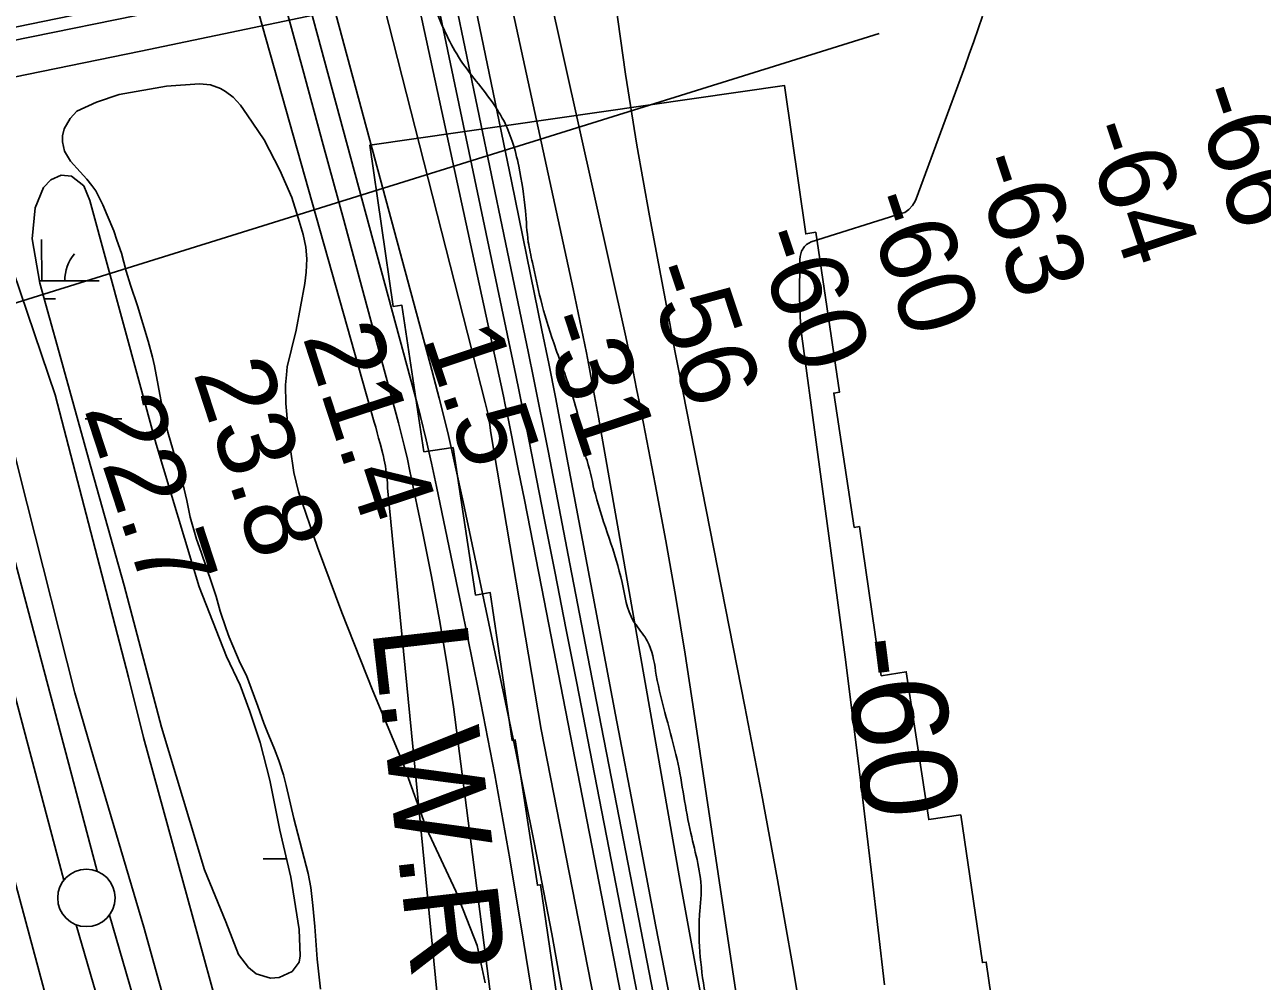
# Model space of a CAD drawing. Extents: x 3405885 to 3443815, y 558517 to 583997.
# Drawn here: x 3412665 to 3413741, y 580269 to 581101 of the extents above; entities that cross this region are included whole.
import ezdxf

# ---------------------------------------------------------------- set-up
doc = ezdxf.new("R2010")
doc.units = 0
for name, color, linetype in [('V-BRDG-OTLN', 7, 'Continuous'), ('V-FLOD-BASE', 7, 'Continuous'), ('V-LEVE-TOET', 7, 'Continuous'), ('V-RIVR-EDGE', 7, 'Continuous'), ('V-RIVR-RANG', 7, 'Continuous'), ('V-ROAD-CNTR', 7, 'Continuous'), ('V-RRAP-RVMT', 7, 'Continuous'), ('V-SITE-VEGE', 7, 'Continuous'), ('V-SURV-LINE', 7, 'Continuous'), ('V-TOPO-DPTH', 7, 'Continuous'), ('V-TOPO-MAJR', 7, 'Continuous'), ('V-TOPO-MINR', 7, 'Continuous'), ('V-TOPO-MINR-IDEN', 7, 'Continuous'), ('V-TOPO-WATR', 7, 'Continuous'), ('V-TOPO-WATR-IDEN', 7, 'Continuous'), ('V-WETL-SWMP', 7, 'Continuous')]:
    doc.layers.add(name, color=color, linetype=linetype)

msp = doc.modelspace()

# ---------------------------------------------------------------- linework, layer by layer
at = {"layer": 'V-BRDG-OTLN'}
for points in [[(3417680.4, 582119.8), (3417601.8, 582104.6), (3417266, 582031.9), (3417072.3, 581991.6), (3416368.4, 581849.5), (3415729.2, 581717.9), (3415183.5, 581606.5), (3414289.2, 581422.5), (3413599.8, 581283.7), (3412908.9, 581139.2), (3412266.4, 581008.4), (3412181.4, 580990.5), (3412075.2, 580969.3), (3411951.8, 580944.2), (3411795.1, 580912.3), (3411642, 580880.6), (3411498.5, 580851.2), (3411034.3, 580756.7), (3410912.4, 580731.2)], [(3411677.7, 580918.3), (3412408.2, 581067.1), (3413000.1, 581190.8), (3413110.1, 581213.7), (3413121.5, 581152.9), (3412941.9, 581114.8), (3412765.6, 581078.1), (3412568.7, 581037.8), (3412280.7, 580978.9), (3411914.4, 580903.8)]]:
    msp.add_lwpolyline(points, dxfattribs=at)
at = {"layer": 'V-FLOD-BASE'}
for points in [[(3412708.3, 580519.9), (3412667, 580684), (3412637.7, 580799.6), (3412608.4, 580882.1), (3412552.9, 581031.3), (3412536.3, 581093.7), (3412510.6, 581183), (3412508.1, 581194.1)], [(3412809.2, 580169), (3412768.3, 580316.1), (3412724.5, 580463.8), (3412708.3, 580519.9)]]:
    msp.add_lwpolyline(points, dxfattribs=at)
at = {"layer": 'V-LEVE-TOET'}
for points in [[(3412547.5, 581149.2), (3412570.5, 581062.7), (3412585.1, 581037.6), (3412612.5, 580998.5), (3412621, 580972.1), (3412655, 580886), (3412691.3, 580779.2), (3412755.1, 580533.4), (3412767.9, 580481)], [(3412611.9, 580517.9), (3412657.3, 580352), (3412706.8, 580167.1), (3412733.3, 580061.4), (3412768.8, 579901.4), (3412809.4, 579723.1), (3412854.8, 579541.2), (3412909.9, 579317.4), (3412945.5, 579162.7), (3412960.5, 579105.7)], [(3412767.9, 580481), (3412806.4, 580341.6), (3412860.6, 580143.7), (3412871.5, 580101.8), (3412901.2, 579957.1), (3412913, 579869.8), (3412926, 579791.3), (3412952.9, 579666.1), (3412992.6, 579509), (3413041.3, 579299.4), (3413080.9, 579138.2), (3413128.6, 578952.8), (3413181, 578759.6), (3413225.8, 578579.5), (3413232.6, 578542.3)]]:
    msp.add_lwpolyline(points, dxfattribs=at)
at = {"layer": 'V-RIVR-EDGE'}
msp.add_spline([(3412820.9, 582098.3), (3412817.8, 582058), (3412815.6, 582029.5), (3412817.7, 582007.9), (3412825.7, 581980.1), (3412850.3, 581879.9), (3412863.7, 581832.7), (3412872, 581799.1), (3412892.3, 581722.3), (3412903.2, 581678.4), (3412909.6, 581634.8), (3412920.5, 581599), (3412934, 581569.3), (3412943.4, 581548.5), (3412954.7, 581511.2), (3412955.3, 581484.9), (3412959.7, 581464), (3412965.1, 581459.6), (3412977.9, 581445), (3412992.4, 581409.1), (3413006.5, 581353.1), (3413015.2, 581302.3), (3413018.7, 581260.3), (3413013.9, 581236.1), (3413008.8, 581220.1), (3413005.1, 581206.5), (3413003.6, 581194.5), (3413004.7, 581180.2), (3413009.3, 581149.1), (3413020.6, 581117.3), (3413042, 581073), (3413073, 581031.3), (3413081, 581018.1), (3413088.7, 580999.8), (3413094.4, 580977.9), (3413100.2, 580939.1), (3413102.7, 580912), (3413106.3, 580894.1), (3413113.5, 580861.9), (3413124.8, 580824.3), (3413140, 580781.4), (3413146.5, 580756.9), (3413148.7, 580740.1), (3413153.8, 580721.8), (3413161, 580692.6), (3413184.2, 580615.7), (3413194, 580582.5), (3413204.2, 580568.2), (3413207.8, 580561.6), (3413214, 580535.3), (3413232.1, 580461.7), (3413244, 580397.7), (3413253, 580345.1), (3413251.9, 580330.8), (3413256.4, 580258.4), (3413262.5, 580217.5), (3413264.6, 580175.4), (3413271.5, 580146.5), (3413278.7, 580117.3), (3413280.2, 580104.8), (3413276.4, 580060.6), (3413276.3, 580025.9), (3413275.6, 580012.4), (3413275.5, 580006.1), (3413277.7, 580003.2), (3413288, 580000.6), (3413298.6, 579998.4), (3413303.7, 579992.2), (3413305.5, 579985.2), (3413310.1, 579953.8), (3413314.5, 579931.1), (3413321, 579914.6), (3413327.2, 579894.5), (3413327.1, 579868.9), (3413323.4, 579842.6), (3413317.9, 579835.3), (3413316, 579824.7), (3413315.6, 579806.5), (3413320, 579780.1), (3413328, 579765.1), (3413335.6, 579758.2), (3413338.2, 579753.4), (3413338.9, 579747.5), (3413338.9, 579742.8), (3413335.5, 579730.7), (3413330.8, 579723.1), (3413327.8, 579714.3), (3413325.2, 579701.2), (3413326.7, 579689.5), (3413332.1, 579675.9), (3413338.3, 579668.2), (3413342.7, 579666.4), (3413352.6, 579666.7), (3413357.3, 579663.4), (3413365.3, 579652.4), (3413371.9, 579635.2), (3413374.8, 579618.4), (3413377.6, 579592.5), (3413379.4, 579557.4), (3413373.8, 579521.6), (3413375.2, 579501.1), (3413382.1, 579476.9), (3413395.1, 579440), (3413408.6, 579400.8), (3413417.6, 579358.8), (3413445.2, 579297.7), (3413449.9, 579271.7), (3413449.8, 579233.3), (3413439.5, 579191.3), (3413438.7, 579182.2), (3413439.8, 579172.7), (3413446, 579161.7), (3413464.9, 579134.6), (3413487.5, 579101.6), (3413497, 579074.9), (3413502.7, 579046.4), (3413506.7, 579018.2), (3413510.6, 578990.8), (3413518.6, 578952.4), (3413529.8, 578903.8), (3413538.1, 578871.6), (3413547.9, 578834.6), (3413558.4, 578787.4), (3413566.7, 578743.2), (3413574.6, 578699.3), (3413585.1, 578637.1), (3413595.2, 578577.2), (3413599.5, 578547.5), (3413610.7, 578516.1), (3413620.2, 578504), (3413626, 578499.2), (3413635.5, 578497), (3413635.9, 578494.4), (3413634.1, 578490.1), (3413632.2, 578487.1), (3413632.2, 578479.5), (3413633.2, 578455), (3413642.2, 578391), (3413644.3, 578359.2), (3413649, 578338.7), (3413656.3, 578322.2), (3413667.6, 578313.8), (3413676, 578309), (3413684.4, 578305.3), (3413688.8, 578300.2), (3413697.9, 578288.5), (3413702.2, 578272.4), (3413709.1, 578250.8), (3413714.9, 578233.2), (3413728.7, 578187.2), (3413734.8, 578151.3), (3413738.8, 578114.4), (3413740.5, 578084), (3413746.7, 578059.2), (3413750.7, 578043.4), (3413751.3, 578020), (3413747.6, 577990.8), (3413742, 577955), (3413736.9, 577934.5), (3413735.4, 577919.6), (3413733.5, 577904.2), (3413737.1, 577880.1), (3413741.4, 577864.7), (3413741.4, 577863.2), (3413750.2, 577865.8), (3413755, 577862.8), (3413760, 577845.7), (3413773.8, 577798.1), (3413781.8, 577765.2), (3413793, 577724.9), (3413797, 577700.4), (3413803.4, 577637.2), (3413804.4, 577613.8), (3413807.7, 577591.8), (3413815.3, 577561.1), (3413829.4, 577524.9), (3413841.8, 577493.8), (3413853.8, 577466), (3413863.2, 577445.5), (3413869.8, 577431.2), (3413869.8, 577426.1), (3413869.7, 577412.9), (3413868.9, 577389.5), (3413869.2, 577353), (3413871, 577339.8), (3413873.9, 577328.5), (3413883, 577306.5), (3413889.5, 577287.9), (3413905.1, 577244.3), (3413913.5, 577211), (3413925.4, 577161.3), (3413947.6, 577101.7), (3413958.8, 577073.5), (3413969, 577057.4), (3413973, 577043.8), (3413979.9, 577014.6), (3414002, 576930.8), (3414004.5, 576907.4), (3414006.3, 576897.2), (3414015, 576880.3), (3414024.5, 576858.8), (3414031.3, 576835.7), (3414040.8, 576799.5), (3414054.2, 576750.1), (3414062.5, 576713.9), (3414069.3, 576679.9), (3414074.4, 576668.5), (3414075.1, 576663.4), (3414103.1, 576586.2), (3414107.4, 576564.6), (3414115.4, 576529.2), (3414119, 576508), (3414142.2, 576433.7), (3414153.5, 576399.3), (3414159.6, 576378.5), (3414164.7, 576348.8), (3414174.1, 576303.8), (3414178, 576275), (3414184.1, 576248.3), (3414191.1, 576234), (3414204.1, 576202.1), (3414212.1, 576179.5), (3414243, 576089.5), (3414264.8, 576025.4), (3414269.5, 576005.7), (3414269.4, 575994.4), (3414267.6, 575989.1)], degree=3, dxfattribs=at)
at = {"layer": 'V-RIVR-RANG'}
msp.add_line((3412586.8, 580837.2), (3413407.7, 581093.5), dxfattribs=at)
at = {"layer": 'V-ROAD-CNTR'}
msp.add_lwpolyline([(3409957, 580546.7), (3410940.8, 580747.1), (3417648.2, 582122.8)], dxfattribs=at)
at = {"layer": 'V-RRAP-RVMT'}
msp.add_lwpolyline([(3413519.8, 580156.2), (3413500.9, 580285.6), (3413497.6, 580285.1), (3413478.8, 580413.6), (3413451, 580409.5), (3413431.3, 580538.2), (3413409.6, 580534.7), (3413390.6, 580664.4), (3413386.1, 580663.7), (3413368.3, 580780.6), (3413373.3, 580781.3), (3413352.6, 580920.5), (3413344, 580919.1), (3413325.4, 581048.3), (3412964.9, 580996.3), (3412985.2, 580855.9), (3412992.8, 580857), (3413011.9, 580729.6), (3413037.2, 580733.2), (3413056.8, 580604.9), (3413069.6, 580607), (3413088.6, 580478.4), (3413091.3, 580478.9), (3413110.6, 580352.4), (3413113.3, 580352.9), (3413130.9, 580232.1)], dxfattribs=at)
at = {"layer": 'V-SITE-VEGE'}
for points in [[(3412727.3, 581033.8), (3412746.9, 581040.3), (3412788, 581047.5), (3412816.7, 581049.6), (3412826.2, 581048.8), (3412835, 581045.5), (3412839.4, 581043), (3412846.1, 581038), (3412852.3, 581031.1), (3412858.3, 581022.6), (3412873.1, 581001), (3412886.7, 580974.4), (3412896.9, 580950.8), (3412902.5, 580933), (3412907, 580918.4), (3412909.1, 580907.5), (3412910.2, 580897.4), (3412909.6, 580885.8), (3412908.3, 580875.8), (3412900.7, 580835.4), (3412896.7, 580818.9), (3412893.1, 580803.4), (3412892.5, 580796.5), (3412891.6, 580787.9), (3412891.9, 580771.6), (3412893.6, 580752.2), (3412895.6, 580733.4), (3412898.8, 580711.4), (3412902.8, 580694.7), (3412919.3, 580646.6), (3412940.6, 580589.6), (3412967.5, 580521.5), (3412993.2, 580459.7), (3413014.1, 580401.8)], [(3412921.9, 580262.1), (3412919.2, 580288), (3412917, 580316.4), (3412915.3, 580334.7), (3412913.7, 580350.6), (3412911.3, 580362.6), (3412898.9, 580410.5), (3412892.2, 580439.2), (3412889.7, 580448.6), (3412885.6, 580460.9), (3412882, 580470.8), (3412875.5, 580486.2), (3412872.6, 580493.3), (3412867.4, 580508.2), (3412861.7, 580523.9), (3412857.6, 580534.8), (3412852.2, 580545.7), (3412842.5, 580568.1), (3412839.8, 580575.6), (3412834.6, 580591), (3412831.1, 580603.6), (3412827.5, 580615), (3412818.1, 580642.1), (3412814, 580653.5), (3412808.5, 580672.5), (3412805.7, 580687), (3412802.2, 580701.8), (3412797.8, 580715), (3412793.8, 580730.5), (3412789.2, 580746.6), (3412784.1, 580770.1), (3412777.7, 580804.3), (3412775.8, 580811.9), (3412772, 580825.8), (3412762.7, 580856.5), (3412756.7, 580874.5), (3412753, 580886.6), (3412748.9, 580902.2), (3412744.7, 580913.6), (3412742.1, 580921.7), (3412736.5, 580935.4), (3412732.8, 580944.3), (3412726.5, 580956.4), (3412723.1, 580961.3), (3412718.7, 580966.8), (3412712.9, 580973), (3412704.6, 580982.4), (3412699.4, 580991.1), (3412697.7, 580999.2), (3412697.6, 581004.4), (3412699.1, 581010.4), (3412704.3, 581019.5), (3412710, 581025.7), (3412727.3, 581033.8)], [(3413014.1, 580401.8), (3413039.7, 580347.4), (3413058.3, 580300.1), (3413065.2, 580267.6)]]:
    msp.add_lwpolyline(points, dxfattribs=at)
at = {"layer": 'V-SURV-LINE'}
for points in [[(3412345.3, 581807.9), (3412727.8, 580364.6)], [(3412698.8, 580356.9), (3412316.3, 581800.2)], [(3412738.4, 580326.4), (3412853.9, 579928.2)], [(3412825.1, 579919.9), (3412709.6, 580318)]]:
    msp.add_lwpolyline(points, dxfattribs=at)
msp.add_circle((3412718.4, 580341.4), 25, dxfattribs=at)
at = {"layer": 'V-TOPO-DPTH'}
for points in [[(3412664.9, 582099.7), (3412797.7, 581548.5), (3412800.3, 581537.6), (3412803.1, 581526.7), (3412805.9, 581515.8), (3412808.7, 581505), (3412840.5, 581386.1), (3412859.4, 581315.8), (3412878.2, 581245.6), (3412897.1, 581175.3), (3412916, 581105.1), (3413003.6, 580780.3), (3413008.8, 580760.2), (3413013.8, 580740), (3413018.5, 580719.7), (3413022.9, 580699.3), (3413044.7, 580594.5), (3413059.4, 580521.5), (3413073.5, 580448.5), (3413086.5, 580375.3), (3413098.9, 580302), (3413146, 580011.8)], [(3412709.1, 582099.9), (3412741.1, 581971.9), (3412821.3, 581676.2), (3412865.2, 581528.8), (3412947.1, 581235.7), (3413065.1, 580772.3), (3413068.5, 580759.5), (3413070.2, 580745.9), (3413113.8, 580487.8), (3413186.9, 580114.7)], [(3413186.9, 580114.7), (3413113.8, 580487.8), (3413070.2, 580745.9), (3413068.5, 580759.5), (3413065.1, 580772.3), (3412947.1, 581235.7), (3412865.2, 581528.8), (3412821.3, 581676.2), (3412741.1, 581971.9), (3412709.1, 582099.9)], [(3413254.4, 580247.2), (3413244.5, 580301.5), (3413234.8, 580355.8), (3413163.6, 580759.6), (3413161.1, 580773.6), (3413158.5, 580787.6), (3413155.9, 580801.6), (3413153.2, 580815.6), (3413150.4, 580829.5), (3413147.6, 580843.5), (3413144.7, 580857.4), (3413141.7, 580871.3), (3413003.1, 581509.2), (3412995.7, 581543.2), (3412988.2, 581577.3), (3412980.7, 581611.3), (3412973.1, 581645.3), (3412871.6, 582100.6)], [(3413254.4, 580247.2), (3413244.5, 580301.5), (3413234.8, 580355.8), (3413163.6, 580759.6), (3413161.1, 580773.6), (3413158.5, 580787.6), (3413155.9, 580801.6), (3413153.2, 580815.6), (3413150.4, 580829.5), (3413147.6, 580843.5), (3413144.7, 580857.4), (3413141.7, 580871.3), (3413003.1, 581509.2), (3412995.7, 581543.2), (3412988.2, 581577.3), (3412980.7, 581611.3), (3412973.1, 581645.3), (3412871.6, 582100.6)], [(3413025.1, 581558.9), (3413187.4, 580829.4), (3413190.6, 580814.4), (3413193.8, 580799.3), (3413196.9, 580784.2), (3413199.9, 580769.1), (3413213, 580701.2), (3413222.2, 580652), (3413231, 580602.8), (3413239.1, 580553.5), (3413246.7, 580504), (3413278.8, 580288.6), (3413283.7, 580255.8)], [(3413025.1, 581558.9), (3413187.4, 580829.4), (3413190.6, 580814.4), (3413193.8, 580799.3), (3413196.9, 580784.2), (3413199.9, 580769.1), (3413213, 580701.2), (3413222.2, 580652), (3413231, 580602.8), (3413239.1, 580553.5), (3413246.7, 580504), (3413278.8, 580288.6), (3413283.7, 580255.8)], [(3412963.3, 581408.5), (3413091.7, 580796.3), (3413094.7, 580781.9), (3413097.6, 580767.5), (3413100.5, 580753.2), (3413103.4, 580738.8), (3413116.6, 580671.8), (3413126, 580624), (3413135.4, 580576.1), (3413144.8, 580528.2), (3413154.1, 580480.3), (3413239, 580043.8)], [(3413239, 580043.8), (3413154.1, 580480.3), (3413144.8, 580528.2), (3413135.4, 580576.1), (3413126, 580624), (3413116.6, 580671.8), (3413103.4, 580738.8), (3413100.5, 580753.2), (3413097.6, 580767.5), (3413094.7, 580781.9), (3413091.7, 580796.3), (3412963.3, 581408.5)], [(3413231.5, 580224.5), (3413213.7, 580316.6), (3413196.1, 580408.6), (3413178.5, 580500.7), (3413161.1, 580592.8), (3413137.4, 580718.5), (3413131.9, 580747.7), (3413126.2, 580777), (3413120.4, 580806.2), (3413114.5, 580835.4), (3413088.1, 580965), (3413068.7, 581058.9), (3413049.1, 581152.8)], [(3413049.1, 581152.8), (3413068.7, 581058.9), (3413088.1, 580965), (3413114.5, 580835.4), (3413120.4, 580806.2), (3413126.2, 580777), (3413131.9, 580747.7), (3413137.4, 580718.5), (3413161.1, 580592.8), (3413178.5, 580500.7), (3413196.1, 580408.6), (3413213.7, 580316.6), (3413231.5, 580224.5)]]:
    msp.add_lwpolyline(points, dxfattribs=at)
at = {"layer": 'V-TOPO-MAJR'}
msp.add_lwpolyline([(3413345.6, 580206.1), (3413332.7, 580281.7), (3413319.4, 580357.2), (3413305.4, 580432.5), (3413291, 580507.8), (3413237.1, 580782.2), (3413234.2, 580796.9), (3413231.3, 580811.6), (3413228.5, 580826.3), (3413225.7, 580841.1), (3413208, 580934.7), (3413197.1, 580996.3), (3413187.1, 581058.1), (3413178.6, 581120.1)], dxfattribs=at)
at = {"layer": 'V-TOPO-MINR'}
for points in [[(3412664.9, 582099.7), (3412797.7, 581548.5), (3412800.3, 581537.6), (3412803.1, 581526.7), (3412805.9, 581515.8), (3412808.7, 581505), (3412840.5, 581386.1), (3412859.4, 581315.8), (3412878.2, 581245.6), (3412897.1, 581175.3), (3412916, 581105.1), (3413003.6, 580780.3), (3413008.8, 580760.2), (3413013.8, 580740), (3413018.5, 580719.7), (3413022.9, 580699.3), (3413044.7, 580594.5), (3413059.4, 580521.5), (3413073.5, 580448.5), (3413086.5, 580375.3), (3413098.9, 580302), (3413146, 580011.8)], [(3412687.5, 582099.8), (3412743.8, 581861), (3412756.7, 581806.1), (3412769.7, 581751.2), (3412782.7, 581696.4), (3412795.7, 581641.5), (3412821, 581534.7), (3412821.4, 581533.3), (3412822.5, 581528.9), (3412826.8, 581512.5), (3412829.4, 581502.8), (3412832, 581493.1), (3412834.6, 581483.5), (3412837.2, 581473.8), (3413017.4, 580806), (3413025.2, 580776.1), (3413032.6, 580746.2), (3413039.5, 580716.1), (3413046.1, 580686), (3413091.7, 580468.9), (3413107.8, 580389.6), (3413123.1, 580310.3), (3413137.4, 580230.7)], [(3412871.6, 582100.6), (3412973.1, 581645.3), (3412980.7, 581611.3), (3412988.2, 581577.3), (3412995.7, 581543.2), (3413003.1, 581509.2), (3413141.7, 580871.3), (3413144.7, 580857.4), (3413147.6, 580843.5), (3413150.4, 580829.5), (3413153.2, 580815.6), (3413155.9, 580801.6), (3413158.5, 580787.6), (3413161.1, 580773.6), (3413163.6, 580759.6), (3413234.8, 580355.8), (3413244.5, 580301.5), (3413254.4, 580247.2)], [(3413283.7, 580255.8), (3413278.8, 580288.6), (3413246.7, 580504), (3413239.1, 580553.5), (3413231, 580602.8), (3413222.2, 580652), (3413213, 580701.2), (3413199.9, 580769.1), (3413196.9, 580784.2), (3413193.8, 580799.3), (3413190.6, 580814.4), (3413187.4, 580829.4), (3413025.1, 581558.9)], [(3412774.5, 581443.9), (3412968.7, 580755.4), (3412970, 580750.8), (3412971.3, 580746.1), (3412972.5, 580741.5), (3412973.8, 580736.8), (3412975.9, 580729), (3412976.3, 580727.5), (3412976.4, 580726.8), (3412977.4, 580722.2), (3412977.9, 580719.6), (3412978.4, 580716.9), (3412978.8, 580714.2), (3412979.4, 580709.4), (3412979.8, 580705.7), (3412980.1, 580701.9), (3412980.3, 580698.2), (3413049.8, 579987.7)], [(3412963.3, 581408.5), (3413091.7, 580796.3), (3413094.7, 580781.9), (3413097.6, 580767.5), (3413100.5, 580753.2), (3413103.4, 580738.8), (3413116.6, 580671.8), (3413126, 580624), (3413135.4, 580576.1), (3413144.8, 580528.2), (3413154.1, 580480.3), (3413239, 580043.8)], [(3413027.9, 581176.9), (3413102.8, 580815.4), (3413107.2, 580793.8), (3413111.6, 580772.2), (3413115.9, 580750.5), (3413120.1, 580728.9), (3413138.8, 580631.9), (3413152.4, 580561.7), (3413166, 580491.5), (3413179.6, 580421.4), (3413193.2, 580351.2), (3413245.4, 580081.8)], [(3413049.1, 581152.8), (3413068.7, 581058.9), (3413088.1, 580965), (3413114.5, 580835.4), (3413120.4, 580806.2), (3413126.2, 580777), (3413131.9, 580747.7), (3413137.4, 580718.5), (3413161.1, 580592.8), (3413178.5, 580500.7), (3413196.1, 580408.6), (3413213.7, 580316.6), (3413231.5, 580224.5)], [(3412888.5, 581127.8), (3412906.5, 581062.2), (3412924.4, 580996.6), (3412942.2, 580930.9), (3412960, 580865.2), (3412989.7, 580754.7), (3412992.4, 580744.2), (3412995, 580733.7), (3412997.5, 580723.2), (3412999.7, 580712.7), (3413011, 580658.7), (3413018.4, 580621), (3413025.4, 580583.3), (3413031.7, 580545.5), (3413037.5, 580507.5), (3413104.9, 579984.7)], [(3413006.3, 581123.6), (3413081, 580777.9), (3413082.6, 580770.5), (3413084.2, 580763.1), (3413085.7, 580755.7), (3413087.2, 580748.2), (3413094.3, 580712.8), (3413099.3, 580687.6), (3413104.3, 580662.4), (3413109.2, 580637.2), (3413114.2, 580612.1), (3413208, 580129.1)], [(3413497.8, 581108.6), (3413494, 581097.5), (3413490.1, 581086.4), (3413486.2, 581075.3), (3413482.2, 581064.3), (3413440, 580949.7), (3413439.1, 580947.6), (3413436.8, 580943.7), (3413433.7, 580940.3), (3413430, 580937.8), (3413427.9, 580937), (3413348.8, 580912.2), (3413344.6, 580909.9), (3413342.9, 580908.2), (3413340.4, 580904), (3413339.2, 580899.3), (3413338.9, 580896.9), (3413338.6, 580864.1), (3413338.7, 580855.5), (3413339, 580847), (3413339.7, 580838.5), (3413340.7, 580830), (3413365.6, 580645.8), (3413378.1, 580550.9), (3413390.1, 580455.9), (3413401.5, 580360.9), (3413412.4, 580265.8)]]:
    msp.add_lwpolyline(points, dxfattribs=at)
at = {"layer": 'V-TOPO-WATR'}
msp.add_lwpolyline([(3413186.9, 580114.7), (3413113.8, 580487.8), (3413070.2, 580745.9), (3413068.5, 580759.5), (3413065.1, 580772.3), (3412947.1, 581235.7), (3412865.2, 581528.8), (3412821.3, 581676.2), (3412741.1, 581971.9), (3412709.1, 582099.9)], dxfattribs=at)
at = {"layer": 'V-WETL-SWMP'}
for p, q in [((3412679.5, 580878.1), (3412679.4, 580914.1)), ((3412677.6, 580878.1), (3412729.5, 580878.3)), ((3412681.7, 580862.7), (3412691.6, 580862.7)), ((3412717.2, 580758.2), (3412749.2, 580758.3)), ((3412872, 580375.4), (3412892.4, 580375.4))]:
    msp.add_line(p, q, dxfattribs=at)
msp.add_lwpolyline([(3412839.5, 580320.7), (3412821.1, 580365.8), (3412783.7, 580490), (3412751.1, 580613.3), (3412720.3, 580723.6), (3412694.6, 580815.8), (3412678, 580876.1), (3412671.2, 580914.8), (3412673.8, 580941.7), (3412681.1, 580959.4), (3412687.4, 580966.2), (3412696.4, 580970.1), (3412705.4, 580969.3), (3412716.2, 580960.8), (3412721.5, 580948.2), (3412779.1, 580736.1), (3412816.5, 580612), (3412840.1, 580551.5), (3412852, 580526.5), (3412860.5, 580503.6), (3412869.6, 580476.5), (3412877.9, 580443.9), (3412886.6, 580400.3), (3412896.1, 580359.5), (3412903.4, 580313.8), (3412904.3, 580291.1), (3412903.5, 580285.6), (3412897.2, 580277.4), (3412886, 580272.1), (3412878.4, 580271.6), (3412866.1, 580275.3), (3412859.3, 580281), (3412850.6, 580292.2)], close=True, dxfattribs=at)
msp.add_arc((3412734.8, 580878.8), 35.2, 139.4574, 181.001, dxfattribs=at)

# ---------------------------------------------------------------- texts
at = {"layer": 'V-RIVR-RANG'}
for s, rotation, p in [('-66', 288.3944, (3413678.1, 581041.4)), ('-64', 288.3944, (3413583.2, 581009.8)), ('-63', 288.3944, (3413487.1, 580981.7)), ('-60', 288.3944, (3413392.9, 580948.2)), ('-60', 288.3944, (3413298, 580916.9)), ('-56', 288.3944, (3413202.6, 580886.8)), ('-31', 288.3944, (3413111.5, 580843.7)), ('21.4', 288.1083, (3412906.1, 580829.5)), ('1.5', 288.3944, (3413011, 580828.9)), ('23.8', 288.1083, (3412811.1, 580798.1)), ('22.7', 288.1083, (3412716.2, 580766.8))]:
    msp.add_text(s, height=67, rotation=rotation, dxfattribs=at).set_placement(p)
at = {"layer": 'V-TOPO-MINR-IDEN'}
msp.add_text('-60', height=83, rotation=277.2223, dxfattribs=at).set_placement((3413376.2, 580565.5))
at = {"layer": 'V-TOPO-WATR-IDEN'}
msp.add_text('L.W.R.P.', height=83, rotation=276.5335, dxfattribs=at).set_placement((3412966.6, 580575.8))

doc.saveas('drawing.dxf')
